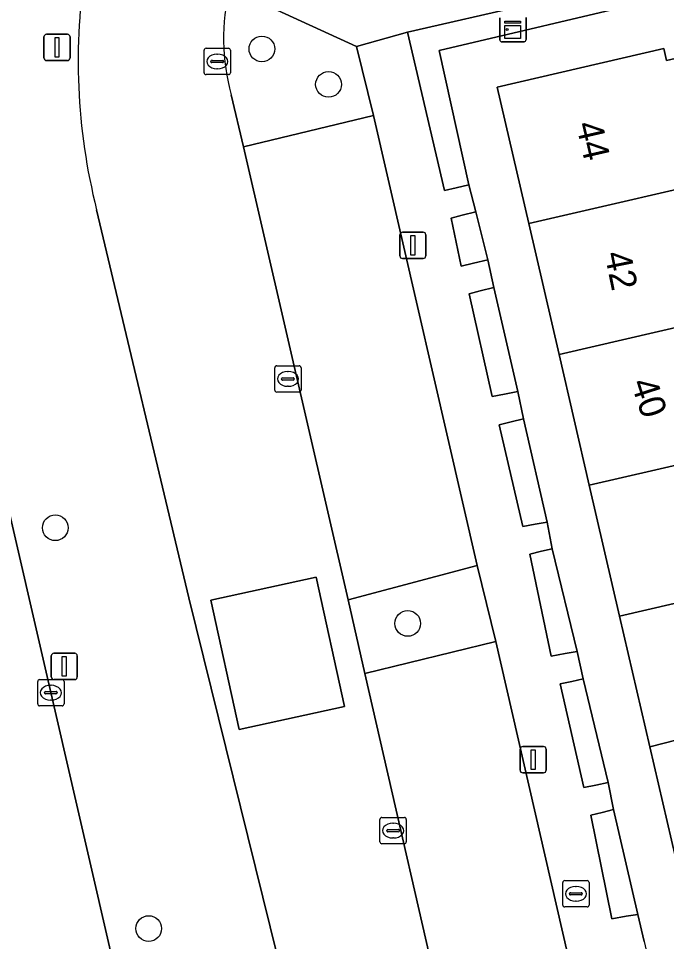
# Model space of a CAD drawing. Extents: x 156412 to 157779, y 382335 to 383768.
# Drawn here: x 157009.32 to 157033.96, y 382933.25 to 382968.31 of the extents above; entities that cross this region are included whole.
import ezdxf

# ---------------------------------------------------------------- set-up
doc = ezdxf.new("R2010")
doc.units = 0
for name, color, linetype in [('IMGEO_Berm_groen', 7, 'Continuous'), ('IMGEO_Boom', 7, 'Continuous'), ('IMGEO_Brandkraan', 7, 'Continuous'), ('IMGEO_Erf', 7, 'Continuous'), ('IMGEO_Groenvoorziening', 7, 'Continuous'), ('IMGEO_Haag', 7, 'Continuous'), ('IMGEO_Kast', 7, 'Continuous'), ('IMGEO_Kolk', 7, 'Continuous'), ('IMGEO_Lichtmast', 7, 'Continuous'), ('IMGEO_OVBaan_gesloten', 7, 'Continuous'), ('IMGEO_Pand', 7, 'Continuous'), ('IMGEO_Pand_nummerreeks', 7, 'Continuous'), ('IMGEO_Parkeervlak_open', 7, 'Continuous'), ('IMGEO_Rijbaan_lokaal_gesloten', 7, 'Continuous'), ('IMGEO_Rijbaan_lokaal_open', 7, 'Continuous'), ('IMGEO_Verkeersbordpaal', 7, 'Continuous'), ('IMGEO_Verkeerseiland_groen', 7, 'Continuous'), ('IMGEO_Voetpad_open', 7, 'Continuous')]:
    doc.layers.add(name, color=color, linetype=linetype)

msp = doc.modelspace()

# ---------------------------------------------------------------- linework, layer by layer
at = {"layer": 'IMGEO_Berm_groen'}
for points in [[(157022.174, 382967.245), (157017.355, 382969.465)], [(157004.746, 382967.732), (157004.966, 382966.852), (157006.102, 382961.936), (157013.082, 382931.735), (157015.315, 382922.757)], [(157017.41, 382965.415), (157017.881, 382963.432), (157022.818, 382964.629), (157022.174, 382967.245)], [(157020.571, 382926.991), (157015.795, 382946.311), (157012.292, 382961.05)]]:
    msp.add_lwpolyline(points, dxfattribs=at)
for centre, radius, start, end in [((157034.609, 382966.692), 23.019, 170.7222, 194.1877), ((157025.002, 382967.543), 7.884, 165.8944, 195.6617)]:
    msp.add_arc(centre, radius, start, end, dxfattribs=at)
at = {"layer": 'IMGEO_Boom'}
for centre in [(157018.574, 382967.156), (157021.108, 382965.811), (157010.721, 382948.967), (157024.117, 382945.333), (157014.272, 382933.743)]:
    msp.add_circle(centre, 0.489, dxfattribs=at)
at = {"layer": 'IMGEO_Brandkraan'}
for p, q in [((157030.012, 382934.637), (157030.012, 382935.489)), ((157030.087, 382935.563), (157030.939, 382935.563)), ((157030.5, 382935.343), (157030.525, 382935.343)), ((157031.013, 382935.489), (157031.013, 382934.637)), ((157030.271, 382935.057), (157030.271, 382935.069)), ((157030.709, 382935.02), (157030.311, 382935.02)), ((157030.314, 382935.106), (157030.712, 382935.106)), ((157030.755, 382935.069), (157030.755, 382935.057)), ((157030.939, 382934.563), (157030.087, 382934.563)), ((157030.523, 382934.783), (157030.498, 382934.783))]:
    msp.add_line(p, q, dxfattribs=at)
for points in [[(157030.012, 382934.637), (157030.012, 382935.489)], [(157030.087, 382935.563), (157030.939, 382935.563)], [(157031.013, 382935.489), (157031.013, 382934.637)], [(157030.939, 382934.563), (157030.087, 382934.563)]]:
    msp.add_lwpolyline(points, dxfattribs=at)
for centre, radius, start, end in [((157030.089, 382935.487), 0.0765, 91.552, 178.448), ((157030.089, 382935.487), 0.0765, 91.552, 178.448), ((157030.937, 382935.487), 0.0765, 1.552, 88.448), ((157030.937, 382935.487), 0.0765, 1.552, 88.448), ((157030.311, 382935.066), 0.0403, 85.8775, 175.7526), ((157030.308, 382935.056), 0.0366, 178.938, 274.7102), ((157030.712, 382935.063), 0.043, 264.8664, 352.4533), ((157030.716, 382935.068), 0.0386, 1.7309, 96.639), ((157030.089, 382934.639), 0.0765, 181.552, 268.448), ((157030.089, 382934.639), 0.0765, 181.552, 268.448), ((157030.937, 382934.639), 0.0765, 271.552, 358.448), ((157030.937, 382934.639), 0.0765, 271.552, 358.448)]:
    msp.add_arc(centre, radius, start, end, dxfattribs=at)
for centre, major_axis, ratio, start_param, end_param in [((157030.499, 382935.063), (-0.387, 0.002), 0.722429, 4.712389, 7.853982), ((157030.524, 382935.063), (-0.39, 0.002), 0.717154, 1.570796, 4.712389)]:
    msp.add_ellipse(centre, major_axis=major_axis, ratio=ratio, start_param=start_param, end_param=end_param, dxfattribs=at)
at = {"layer": 'IMGEO_Erf'}
for points in [[(157035.623, 382930.709), (157034.472, 382935.677), (157033.321, 382940.646), (157032.17, 382945.615), (157031.02, 382950.583), (157029.869, 382955.551), (157028.718, 382960.52), (157027.516, 382965.71), (157033.849, 382967.171), (157033.954, 382966.714), (157035.505, 382967.074), (157035.4, 382967.532), (157035.975, 382967.665), (157042.956, 382969.272)], [(157033.388, 382968.999), (157025.312, 382967.098), (157026.438, 382961.994), (157026.708, 382960.971), (157027.168, 382959.149), (157027.386, 382958.094), (157028.3, 382954.14), (157028.516, 382953.106), (157029.418, 382949.184), (157029.615, 382948.171), (157030.556, 382944.265), (157030.788, 382943.23), (157031.737, 382939.296), (157031.943, 382938.26), (157032.864, 382934.281), (157033.111, 382933.246), (157034.001, 382929.316), (157034.235, 382928.299), (157035.422, 382923.7), (157035.726, 382922.668), (157037.556, 382918.474), (157038.079, 382917.533), (157040.336, 382913.453)]]:
    msp.add_lwpolyline(points, dxfattribs=at)
at = {"layer": 'IMGEO_Groenvoorziening'}
for points in [[(157025.511, 382961.78), (157025.955, 382961.882), (157026.438, 382961.994), (157025.312, 382967.098), (157033.388, 382968.999), (157033.314, 382969.36), (157033.206, 382969.885), (157024.116, 382967.788)], [(157027.168, 382959.149), (157026.708, 382960.971), (157026.188, 382960.838), (157025.771, 382960.731), (157026.15, 382958.901), (157026.62, 382959.016)], [(157027.799, 382954.046), (157028.3, 382954.14), (157027.386, 382958.094), (157026.87, 382957.962), (157026.448, 382957.854), (157027.327, 382953.958)], [(157029.418, 382949.184), (157028.516, 382953.106), (157028.05, 382952.988), (157027.594, 382952.872), (157028.489, 382949.012), (157028.968, 382949.101)], [(157030.556, 382944.265), (157029.615, 382948.171), (157029.206, 382948.073), (157028.762, 382947.967), (157029.575, 382944.093), (157030.108, 382944.186)], [(157029.917, 382943.039), (157030.819, 382939.1), (157031.265, 382939.195), (157031.737, 382939.296), (157030.788, 382943.23), (157030.352, 382943.134)], [(157032.864, 382934.281), (157031.943, 382938.26), (157031.506, 382938.155), (157031.08, 382938.053), (157031.876, 382934.118), (157032.422, 382934.208)]]:
    msp.add_lwpolyline(points, close=True, dxfattribs=at)
at = {"layer": 'IMGEO_Haag'}
for points in [[(157025.511, 382961.78), (157025.955, 382961.882), (157026.438, 382961.994), (157025.312, 382967.098), (157033.388, 382968.999), (157033.314, 382969.36), (157033.206, 382969.885), (157024.116, 382967.788)], [(157027.168, 382959.149), (157026.708, 382960.971), (157026.188, 382960.838), (157025.771, 382960.731), (157026.15, 382958.901), (157026.62, 382959.016)], [(157027.799, 382954.046), (157028.3, 382954.14), (157027.386, 382958.094), (157026.87, 382957.962), (157026.448, 382957.854), (157027.327, 382953.958)], [(157029.418, 382949.184), (157028.516, 382953.106), (157028.05, 382952.988), (157027.594, 382952.872), (157028.489, 382949.012), (157028.968, 382949.101)], [(157030.556, 382944.265), (157029.615, 382948.171), (157029.206, 382948.073), (157028.762, 382947.967), (157029.575, 382944.093), (157030.108, 382944.186)], [(157029.917, 382943.039), (157030.819, 382939.1), (157031.265, 382939.195), (157031.737, 382939.296), (157030.788, 382943.23), (157030.352, 382943.134)], [(157032.864, 382934.281), (157031.943, 382938.26), (157031.506, 382938.155), (157031.08, 382938.053), (157031.876, 382934.118), (157032.422, 382934.208)]]:
    msp.add_lwpolyline(points, close=True, dxfattribs=at)
at = {"layer": 'IMGEO_Kast'}
for p, q in [((157027.616, 382967.502), (157027.616, 382968.343)), ((157027.616, 382968.343), (157027.616, 382967.502)), ((157028.616, 382968.352), (157028.616, 382967.511)), ((157028.616, 382967.511), (157028.616, 382968.352)), ((157028.541, 382967.427), (157027.7, 382967.427)), ((157027.7, 382967.427), (157028.541, 382967.427))]:
    msp.add_line(p, q, dxfattribs=at)
for points in [[(157027.811, 382968.217), (157028.411, 382968.217), (157028.411, 382968.132), (157027.811, 382968.132), (157027.811, 382968.217)], [(157027.811, 382968.042), (157028.411, 382968.042), (157028.411, 382967.553), (157027.811, 382967.553), (157027.811, 382968.042)]]:
    msp.add_lwpolyline(points, dxfattribs=at)
msp.add_circle((157027.895, 382967.891), 0.0377, dxfattribs=at)
for centre, start, end in [((157027.694, 382967.505), 182.4484, 274.2845), ((157027.694, 382967.505), 182.4484, 274.2845), ((157028.538, 382967.505), 272.4484, 4.2845), ((157028.538, 382967.505), 272.4484, 4.2845)]:
    msp.add_arc(centre, 0.0779, start, end, dxfattribs=at)
at = {"layer": 'IMGEO_Kolk'}
for p, q in [((157016.452, 382967.181), (157017.304, 382967.181)), ((157016.377, 382966.255), (157016.377, 382967.107)), ((157016.865, 382966.961), (157016.89, 382966.961)), ((157017.378, 382967.107), (157017.378, 382966.255)), ((157016.636, 382966.675), (157016.636, 382966.687)), ((157017.074, 382966.638), (157016.676, 382966.638)), ((157016.679, 382966.724), (157017.077, 382966.724)), ((157017.12, 382966.687), (157017.12, 382966.675)), ((157017.304, 382966.181), (157016.452, 382966.181)), ((157016.888, 382966.401), (157016.863, 382966.401)), ((157019.064, 382954.195), (157019.064, 382955.047)), ((157019.139, 382955.121), (157019.991, 382955.121)), ((157019.552, 382954.901), (157019.577, 382954.901)), ((157020.065, 382955.047), (157020.065, 382954.195)), ((157019.323, 382954.615), (157019.323, 382954.627)), ((157019.761, 382954.578), (157019.363, 382954.578)), ((157019.366, 382954.664), (157019.764, 382954.664)), ((157019.807, 382954.627), (157019.807, 382954.615)), ((157019.575, 382954.341), (157019.55, 382954.341)), ((157019.991, 382954.121), (157019.139, 382954.121)), ((157010.052, 382942.277), (157010.052, 382943.129)), ((157010.127, 382943.203), (157010.979, 382943.203)), ((157010.54, 382942.983), (157010.565, 382942.983)), ((157011.053, 382943.129), (157011.053, 382942.277)), ((157010.311, 382942.697), (157010.311, 382942.709)), ((157010.749, 382942.66), (157010.351, 382942.66)), ((157010.354, 382942.746), (157010.752, 382942.746)), ((157010.795, 382942.709), (157010.795, 382942.697)), ((157010.563, 382942.423), (157010.538, 382942.423)), ((157010.979, 382942.203), (157010.127, 382942.203)), ((157023.063, 382937.037), (157023.063, 382937.889)), ((157023.138, 382937.963), (157023.99, 382937.963)), ((157023.551, 382937.743), (157023.576, 382937.743)), ((157024.064, 382937.889), (157024.064, 382937.037)), ((157023.322, 382937.457), (157023.322, 382937.469)), ((157023.76, 382937.42), (157023.362, 382937.42)), ((157023.365, 382937.506), (157023.763, 382937.506)), ((157023.806, 382937.469), (157023.806, 382937.457)), ((157023.574, 382937.183), (157023.549, 382937.183)), ((157023.99, 382936.963), (157023.138, 382936.963))]:
    msp.add_line(p, q, dxfattribs=at)
for points in [[(157016.452, 382967.181), (157017.304, 382967.181)], [(157016.377, 382966.255), (157016.377, 382967.107)], [(157017.378, 382967.107), (157017.378, 382966.255)], [(157017.304, 382966.181), (157016.452, 382966.181)], [(157019.064, 382954.195), (157019.064, 382955.047)], [(157019.139, 382955.121), (157019.991, 382955.121)], [(157020.065, 382955.047), (157020.065, 382954.195)], [(157019.991, 382954.121), (157019.139, 382954.121)], [(157010.052, 382942.277), (157010.052, 382943.129)], [(157010.127, 382943.203), (157010.979, 382943.203)], [(157011.053, 382943.129), (157011.053, 382942.277)], [(157010.979, 382942.203), (157010.127, 382942.203)], [(157023.063, 382937.037), (157023.063, 382937.889)], [(157023.138, 382937.963), (157023.99, 382937.963)], [(157024.064, 382937.889), (157024.064, 382937.037)], [(157023.99, 382936.963), (157023.138, 382936.963)]]:
    msp.add_lwpolyline(points, dxfattribs=at)
for centre, radius, start, end in [((157016.454, 382967.105), 0.0765, 91.552, 178.448), ((157016.454, 382967.105), 0.0765, 91.552, 178.448), ((157017.302, 382967.105), 0.0765, 1.552, 88.448), ((157017.302, 382967.105), 0.0765, 1.552, 88.448), ((157016.676, 382966.684), 0.0403, 85.8775, 175.7526), ((157016.673, 382966.674), 0.0366, 178.938, 274.7102), ((157017.077, 382966.681), 0.043, 264.8664, 352.4533), ((157017.081, 382966.686), 0.0386, 1.7309, 96.639), ((157016.454, 382966.257), 0.0765, 181.552, 268.448), ((157016.454, 382966.257), 0.0765, 181.552, 268.448), ((157017.302, 382966.257), 0.0765, 271.552, 358.448), ((157017.302, 382966.257), 0.0765, 271.552, 358.448), ((157019.141, 382955.045), 0.0765, 91.552, 178.448), ((157019.141, 382955.045), 0.0765, 91.552, 178.448), ((157019.989, 382955.045), 0.0765, 1.552, 88.448), ((157019.989, 382955.045), 0.0765, 1.552, 88.448), ((157019.363, 382954.624), 0.0403, 85.8775, 175.7526), ((157019.36, 382954.614), 0.0366, 178.938, 274.7102), ((157019.764, 382954.621), 0.043, 264.8664, 352.4533), ((157019.768, 382954.626), 0.0386, 1.7309, 96.639), ((157019.141, 382954.197), 0.0765, 181.552, 268.448), ((157019.141, 382954.197), 0.0765, 181.552, 268.448), ((157019.989, 382954.197), 0.0765, 271.552, 358.448), ((157019.989, 382954.197), 0.0765, 271.552, 358.448), ((157010.129, 382943.127), 0.0765, 91.552, 178.448), ((157010.129, 382943.127), 0.0765, 91.552, 178.448), ((157010.977, 382943.127), 0.0765, 1.552, 88.448), ((157010.977, 382943.127), 0.0765, 1.552, 88.448), ((157010.351, 382942.706), 0.0403, 85.8775, 175.7526), ((157010.348, 382942.696), 0.0366, 178.938, 274.7102), ((157010.752, 382942.703), 0.043, 264.8664, 352.4533), ((157010.756, 382942.708), 0.0386, 1.7309, 96.639), ((157010.129, 382942.279), 0.0765, 181.552, 268.448), ((157010.129, 382942.279), 0.0765, 181.552, 268.448), ((157010.977, 382942.279), 0.0765, 271.552, 358.448), ((157010.977, 382942.279), 0.0765, 271.552, 358.448), ((157023.14, 382937.887), 0.0765, 91.552, 178.448), ((157023.14, 382937.887), 0.0765, 91.552, 178.448), ((157023.988, 382937.887), 0.0765, 1.552, 88.448), ((157023.988, 382937.887), 0.0765, 1.552, 88.448), ((157023.362, 382937.466), 0.0403, 85.8775, 175.7526), ((157023.359, 382937.456), 0.0366, 178.938, 274.7102), ((157023.763, 382937.463), 0.043, 264.8664, 352.4533), ((157023.767, 382937.468), 0.0386, 1.7309, 96.639), ((157023.14, 382937.039), 0.0765, 181.552, 268.448), ((157023.14, 382937.039), 0.0765, 181.552, 268.448), ((157023.988, 382937.039), 0.0765, 271.552, 358.448), ((157023.988, 382937.039), 0.0765, 271.552, 358.448)]:
    msp.add_arc(centre, radius, start, end, dxfattribs=at)
for centre, major_axis, ratio, start_param, end_param in [((157016.864, 382966.681), (-0.387, 0.002), 0.722429, 4.712389, 7.853982), ((157016.889, 382966.681), (-0.39, 0.002), 0.717154, 1.570796, 4.712389), ((157019.551, 382954.621), (-0.387, 0.002), 0.722429, 4.712389, 7.853982), ((157019.576, 382954.621), (-0.39, 0.002), 0.717154, 1.570796, 4.712389), ((157010.539, 382942.703), (-0.387, 0.002), 0.722429, 4.712389, 7.853982), ((157010.564, 382942.703), (-0.39, 0.002), 0.717154, 1.570796, 4.712389), ((157023.55, 382937.463), (-0.387, 0.002), 0.722429, 4.712389, 7.853982), ((157023.575, 382937.463), (-0.39, 0.002), 0.717154, 1.570796, 4.712389)]:
    msp.add_ellipse(centre, major_axis=major_axis, ratio=ratio, start_param=start_param, end_param=end_param, dxfattribs=at)
at = {"layer": 'IMGEO_Lichtmast'}
for p, q in [((157023.917, 382960.196), (157024.707, 382960.196)), ((157024.707, 382960.196), (157023.917, 382960.196)), ((157023.817, 382959.296), (157023.817, 382960.096)), ((157023.817, 382960.096), (157023.817, 382959.296)), ((157024.807, 382960.096), (157024.807, 382959.296)), ((157024.807, 382959.296), (157024.807, 382960.096)), ((157024.707, 382959.196), (157023.917, 382959.196)), ((157023.917, 382959.196), (157024.707, 382959.196)), ((157010.569, 382943.301), (157010.569, 382944.101)), ((157010.569, 382944.101), (157010.569, 382943.301)), ((157010.669, 382944.201), (157011.459, 382944.201)), ((157011.459, 382944.201), (157010.669, 382944.201)), ((157011.559, 382944.101), (157011.559, 382943.301)), ((157011.559, 382943.301), (157011.559, 382944.101)), ((157011.459, 382943.201), (157010.669, 382943.201)), ((157010.669, 382943.201), (157011.459, 382943.201)), ((157028.39, 382939.758), (157028.39, 382940.558)), ((157028.39, 382940.558), (157028.39, 382939.758)), ((157028.49, 382940.658), (157029.28, 382940.658)), ((157029.28, 382940.658), (157028.49, 382940.658)), ((157029.38, 382940.558), (157029.38, 382939.758)), ((157029.38, 382939.758), (157029.38, 382940.558)), ((157029.28, 382939.658), (157028.49, 382939.658)), ((157028.49, 382939.658), (157029.28, 382939.658))]:
    msp.add_line(p, q, dxfattribs=at)
for points in [[(157024.237, 382960.071), (157024.387, 382960.071), (157024.387, 382959.321), (157024.237, 382959.321), (157024.237, 382960.071)], [(157010.989, 382944.076), (157011.139, 382944.076), (157011.139, 382943.326), (157010.989, 382943.326), (157010.989, 382944.076)], [(157028.81, 382940.533), (157028.96, 382940.533), (157028.96, 382939.783), (157028.81, 382939.783), (157028.81, 382940.533)]]:
    msp.add_lwpolyline(points, dxfattribs=at)
for centre, start, end in [((157023.917, 382960.096), 90, 180), ((157023.917, 382960.096), 90, 180), ((157024.707, 382960.096), 0, 90), ((157024.707, 382960.096), 360, 90), ((157023.917, 382959.296), 180, 270), ((157023.917, 382959.296), 180, 270), ((157024.707, 382959.296), 270, 0), ((157024.707, 382959.296), 270, 0), ((157010.669, 382944.101), 90, 180), ((157010.669, 382944.101), 90, 180), ((157011.459, 382944.101), 0, 90), ((157011.459, 382944.101), 360, 90), ((157010.669, 382943.301), 180, 270), ((157010.669, 382943.301), 180, 270), ((157011.459, 382943.301), 270, 0), ((157011.459, 382943.301), 270, 0), ((157028.49, 382940.558), 90, 180), ((157028.49, 382940.558), 90, 180), ((157029.28, 382940.558), 0, 90), ((157029.28, 382940.558), 360, 90), ((157028.49, 382939.758), 180, 270), ((157028.49, 382939.758), 180, 270), ((157029.28, 382939.758), 270, 0), ((157029.28, 382939.758), 270, 0)]:
    msp.add_arc(centre, 0.1, start, end, dxfattribs=at)
at = {"layer": 'IMGEO_OVBaan_gesloten'}
msp.add_lwpolyline([(157015.315, 382922.757), (157013.082, 382931.735), (157006.102, 382961.936)], dxfattribs=at)
at = {"layer": 'IMGEO_Pand'}
for points in [[(157037.156, 382962.551), (157035.975, 382967.665), (157035.4, 382967.532), (157035.505, 382967.074), (157033.954, 382966.714), (157033.849, 382967.171), (157027.516, 382965.71), (157028.718, 382960.52), (157037.174, 382962.473)], [(157040.878, 382958.094), (157039.723, 382963.13), (157037.156, 382962.551), (157037.174, 382962.473), (157028.718, 382960.52), (157029.869, 382955.551)], [(157040.878, 382958.094), (157029.869, 382955.551), (157031.02, 382950.583), (157040.047, 382952.668), (157040.852, 382952.854), (157042.019, 382953.124)], [(157040.852, 382952.854), (157040.047, 382952.668), (157031.02, 382950.583), (157032.17, 382945.615), (157040.31, 382947.494), (157040.832, 382947.615), (157041.999, 382947.885), (157040.903, 382952.633)], [(157040.832, 382947.615), (157040.31, 382947.494), (157032.17, 382945.615), (157033.321, 382940.646), (157041.927, 382942.849), (157044.268, 382943.383), (157044.771, 382943.498), (157044.169, 382946.135), (157041.326, 382945.487), (157040.891, 382947.397)], [(157034.472, 382935.677), (157045.462, 382938.216), (157044.268, 382943.383), (157041.927, 382942.849), (157033.321, 382940.646)]]:
    msp.add_lwpolyline(points, close=True, dxfattribs=at)
at = {"layer": 'IMGEO_Parkeervlak_open'}
for points in [[(157017.881, 382963.432), (157021.849, 382946.226), (157026.752, 382947.531), (157022.818, 382964.629)], [(157027.462, 382944.644), (157022.489, 382943.43), (157025.841, 382928.792), (157030.834, 382929.979)]]:
    msp.add_lwpolyline(points, close=True, dxfattribs=at)
at = {"layer": 'IMGEO_Rijbaan_lokaal_gesloten'}
for points in [[(157017.881, 382963.432), (157017.41, 382965.415)], [(157027.746, 382921.036), (157025.841, 382928.792), (157022.489, 382943.43), (157021.849, 382946.226), (157017.881, 382963.432)], [(157012.292, 382961.05), (157015.795, 382946.311), (157020.571, 382926.991)]]:
    msp.add_lwpolyline(points, dxfattribs=at)
msp.add_lwpolyline([(157020.632, 382947.096), (157021.709, 382942.173), (157017.715, 382941.299), (157016.638, 382946.222)], close=True, dxfattribs=at)
for centre, radius, start, end in [((157034.609, 382966.692), 23.019, 170.7222, 194.1877), ((157025.002, 382967.543), 7.884, 165.8944, 195.6617)]:
    msp.add_arc(centre, radius, start, end, dxfattribs=at)
at = {"layer": 'IMGEO_Rijbaan_lokaal_open'}
msp.add_lwpolyline([(157017.715, 382941.299), (157021.709, 382942.173), (157020.632, 382947.096), (157016.638, 382946.222)], close=True, dxfattribs=at)
at = {"layer": 'IMGEO_Verkeersbordpaal'}
for p, q in [((157010.292, 382966.814), (157010.292, 382967.614)), ((157010.292, 382967.614), (157010.292, 382966.814)), ((157010.392, 382967.714), (157011.182, 382967.714)), ((157011.182, 382967.714), (157010.392, 382967.714)), ((157011.282, 382967.614), (157011.282, 382966.814)), ((157011.282, 382966.814), (157011.282, 382967.614)), ((157011.182, 382966.714), (157010.392, 382966.714)), ((157010.392, 382966.714), (157011.182, 382966.714))]:
    msp.add_line(p, q, dxfattribs=at)
msp.add_lwpolyline([(157010.712, 382967.589), (157010.862, 382967.589), (157010.862, 382966.839), (157010.712, 382966.839), (157010.712, 382967.589)], dxfattribs=at)
for centre, start, end in [((157010.392, 382967.614), 90, 180), ((157010.392, 382967.614), 90, 180), ((157011.182, 382967.614), 0, 90), ((157011.182, 382967.614), 360, 90), ((157010.392, 382966.814), 180, 270), ((157010.392, 382966.814), 180, 270), ((157011.182, 382966.814), 270, 0), ((157011.182, 382966.814), 270, 0)]:
    msp.add_arc(centre, 0.1, start, end, dxfattribs=at)
at = {"layer": 'IMGEO_Verkeerseiland_groen'}
msp.add_lwpolyline([(157026.752, 382947.531), (157021.849, 382946.226), (157022.489, 382943.43), (157027.462, 382944.644)], close=True, dxfattribs=at)
at = {"layer": 'IMGEO_Voetpad_open'}
for points in [[(157017.355, 382969.465), (157022.174, 382967.245), (157024.116, 382967.788), (157033.206, 382969.885)], [(157026.438, 382961.994), (157025.955, 382961.882), (157025.511, 382961.78), (157024.116, 382967.788), (157022.174, 382967.245), (157022.818, 382964.629), (157026.752, 382947.531), (157027.462, 382944.644), (157030.834, 382929.979), (157025.841, 382928.792), (157027.746, 382921.036), (157032.645, 382922.627)], [(157033.111, 382933.246), (157032.864, 382934.281), (157032.422, 382934.208), (157031.876, 382934.118), (157031.08, 382938.053), (157031.506, 382938.155), (157031.943, 382938.26), (157031.737, 382939.296), (157031.265, 382939.195), (157030.819, 382939.1), (157029.917, 382943.039), (157030.352, 382943.134), (157030.788, 382943.23), (157030.556, 382944.265), (157030.108, 382944.186), (157029.575, 382944.093), (157028.762, 382947.967), (157029.206, 382948.073), (157029.615, 382948.171), (157029.418, 382949.184), (157028.968, 382949.101), (157028.489, 382949.012), (157027.594, 382952.872), (157028.05, 382952.988), (157028.516, 382953.106), (157028.3, 382954.14), (157027.799, 382954.046), (157027.327, 382953.958), (157026.448, 382957.854), (157026.87, 382957.962), (157027.386, 382958.094), (157027.168, 382959.149), (157026.62, 382959.016), (157026.15, 382958.901), (157025.771, 382960.731), (157026.188, 382960.838), (157026.708, 382960.971), (157026.438, 382961.994)]]:
    msp.add_lwpolyline(points, dxfattribs=at)

# ---------------------------------------------------------------- texts
at = {"layer": 'IMGEO_Pand_nummerreeks'}
for s, rotation, p in [('44', 282.9908, (157030.512, 382964.298)), ('42', 281.4662, (157031.597, 382959.379)), ('40', 287.9964, (157032.594, 382954.476))]:
    msp.add_text(s, height=1, rotation=rotation, dxfattribs=at).set_placement(p)

doc.saveas('drawing.dxf')
